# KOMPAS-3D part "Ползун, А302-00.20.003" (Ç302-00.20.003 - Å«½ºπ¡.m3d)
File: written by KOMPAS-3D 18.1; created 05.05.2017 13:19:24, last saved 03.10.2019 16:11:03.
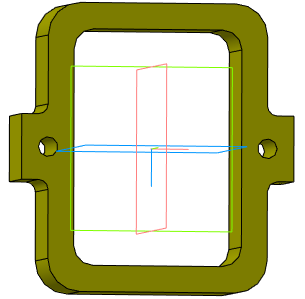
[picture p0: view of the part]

Document properties: Автор: Милов; Организация: Милов; Полное имя файла: D:\Мембранные насосы\Мембранный электропривод\А302-00.00.000 - ASTRA-302 (МЭ200)\3Д\А302-00.20.003 - Ползун.m3d

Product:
- Part/product: Ползун  | designation А302-00.20.003
    Материал: Полиамид П-12Б-20  ТУ 6-05-898-73 (density 1020 kg/m3)
    Масса: 0.0527789
    Раздел спецификации: Детали
    Форматы листов документа: A3

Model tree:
1. Эскиз:1
2. Операция выдавливания:3
     Расстояние 1 = 21
3. Скругление:1  (with: Операция выдавливания:3)
     Радиус = 6
4. Скругление:2  (with: Операция выдавливания:3)
     Радиус = 10
5. Эскиз:6  (with: Операция выдавливания:3)
6. Отверстие:1  (with: Операция выдавливания:3)
     Глубина выреза = 21; Диаметр отверстия = 6; Угол конуса торца = 118; Координата X = 34
7. M5  (labels: cil0_24705-2004 coarse)
     Длина резьбы = 21; Шаг резьбы = 0.8; Номинальный диаметр резьбы = 5
8. Скругление:4  (with: Операция выдавливания:3)
     Радиус = 3
9. Зеркальный массив:2
10. Экземпляр ( 1 )
11. Экземпляр ( 2 )  (with: Отверстие:1, Скругление:4)
12. Фаска:2  (with: Операция выдавливания:3)  (labels: Полиамид П-12Б-20  ТУ 6-05-898-73)
     Угол = 45; Длина 1 = 0.5; Длина 2 = 0.5

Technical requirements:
  Gost Type A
